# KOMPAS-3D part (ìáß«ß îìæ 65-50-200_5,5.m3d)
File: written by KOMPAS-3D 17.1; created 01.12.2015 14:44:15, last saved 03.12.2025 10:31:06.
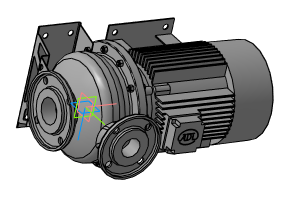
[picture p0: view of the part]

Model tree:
1. Операция без истории:3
